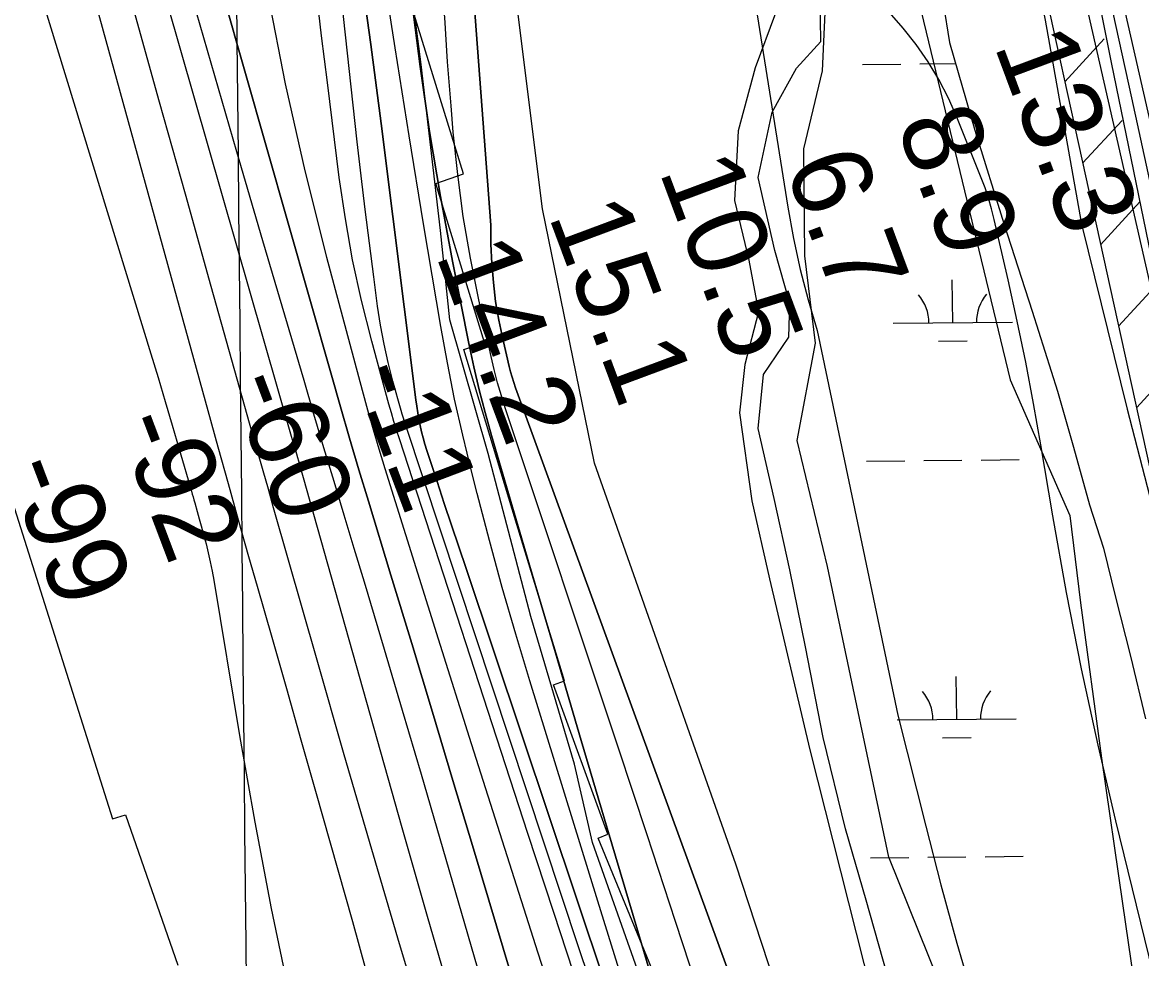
# Model space of a CAD drawing. Extents: x 3625074 to 3663148, y 511451 to 537151.
# Drawn here: x 3634334 to 3635272, y 523291 to 524076 of the extents above; entities that cross this region are included whole.
import ezdxf

# ---------------------------------------------------------------- set-up
doc = ezdxf.new("R2010")
doc.units = 0
for name, color, linetype in [('V-BORW-LINE', 7, 'Continuous'), ('V-FLOD-BASE', 7, 'Continuous'), ('V-GRID-MAJR', 7, 'Continuous'), ('V-LEVE-TOET', 7, 'Continuous'), ('V-RIVR-EDGE', 7, 'Continuous'), ('V-RIVR-RANG', 7, 'Continuous'), ('V-ROAD-CNTR', 7, 'Continuous'), ('V-RRAP-FSHR', 7, 'Continuous'), ('V-RRAP-RVMT', 7, 'Continuous'), ('V-SITE-VEGE', 7, 'Continuous'), ('V-SURV-LINE', 7, 'Continuous'), ('V-TOPO-DPTH', 7, 'Continuous'), ('V-TOPO-MAJR', 7, 'Continuous'), ('V-TOPO-MINR', 7, 'Continuous'), ('V-TOPO-WATR', 7, 'Continuous'), ('V-WETL-SWMP', 7, 'Continuous')]:
    doc.layers.add(name, color=color, linetype=linetype)

msp = doc.modelspace()

# ---------------------------------------------------------------- linework, layer by layer
at = {"layer": 'V-BORW-LINE'}
msp.add_lwpolyline([(3635135.42, 523189.52), (3635060.21, 523376.18), (3635008.87, 523620.11), (3634983.37, 523725.78), (3634998.84, 523807.41), (3634989.96, 523880.66), (3634989.06, 523970.28), (3635004.7, 524035.62), (3635011.38, 524182.35), (3634977.64, 524296.09), (3634968.43, 524401.92), (3634984.32, 524442.82), (3635008.84, 524434.92), (3635033.61, 524402.58), (3635050.72, 524321.27), (3635059.77, 524231.73), (3635085.6, 524093.47), (3635162.12, 523776.46), (3635212.15, 523662.89), (3635221.03, 523589.64), (3635238.63, 523459.45), (3635256.15, 523337.4), (3635282.39, 523158.41)], dxfattribs=at)
at = {"layer": 'V-FLOD-BASE'}
msp.add_lwpolyline([(3635088.85, 524732.57), (3635135.28, 524536.62), (3635174.93, 524366.83), (3635209.04, 524231.05), (3635246.81, 524042.7), (3635280.14, 523880.8)], dxfattribs=at)
at = {"layer": 'V-GRID-MAJR'}
msp.add_spline([(3634583.66, 516913.04), (3634524.61, 522971.79), (3634465.55, 529032.47), (3634406.49, 535093.17), (3634406.47, 535095.09)], degree=3, dxfattribs=at)
at = {"layer": 'V-LEVE-TOET'}
msp.add_lwpolyline([(3635064.8, 524659.03), (3635094.14, 524546.21), (3635125.53, 524397.38), (3635160.9, 524235.18), (3635191.36, 524078.23), (3635222.01, 523907.06), (3635260.32, 523752.09), (3635297.55, 523607.28)], dxfattribs=at)
at = {"layer": 'V-RIVR-EDGE'}
msp.add_lwpolyline([(3634849.5, 523281.91), (3634811.77, 523388.62), (3634796.62, 523454.22), (3634760.16, 523578.08), (3634724.35, 523714.81), (3634692.15, 523827.01), (3634684.37, 523901.79), (3634668.17, 524040.92), (3634659.75, 524105.89), (3634647.21, 524237.04), (3634642.6, 524355.31), (3634629.99, 524460.12), (3634608.23, 524582.1)], dxfattribs=at)
at = {"layer": 'V-ROAD-CNTR'}
msp.add_lwpolyline([(3635138.94, 524570.37), (3635155.25, 524500.89), (3635189.26, 524351.75), (3635229.41, 524169.77), (3635263.93, 524013.09), (3635304.9, 523824.43), (3635347.31, 523635.48), (3635391.23, 523453.76), (3635441.04, 523243.56)], dxfattribs=at)
at = {"layer": 'V-RRAP-FSHR'}
for p, q in [((3635207.83, 524026.59), (3635240.88, 524062.53)), ((3635222.86, 523958.22), (3635255.91, 523994.17)), ((3635237.89, 523889.86), (3635270.94, 523925.8)), ((3635252.92, 523821.49), (3635285.97, 523857.43)), ((3635267.95, 523753.12), (3635301, 523789.06))]:
    msp.add_line(p, q, dxfattribs=at)
msp.add_lwpolyline([(3635086.48, 524584.28), (3635168.39, 524205.98), (3635317.67, 523526.98)], dxfattribs=at)
at = {"layer": 'V-RRAP-RVMT'}
for p, q in [((3634703.76, 523949.28), (3634661.9, 524083.9)), ((3634680.5, 523941.35), (3634703.76, 523949.28)), ((3634721.19, 523807.95), (3634680.5, 523941.35)), ((3634703.88, 523801.95), (3634721.19, 523807.95)), ((3634744.52, 523668.11), (3634703.88, 523801.95)), ((3634318.88, 523695.23), (3634409.45, 523408.4)), ((3634788.48, 523524.06), (3634744.52, 523668.11)), ((3634779.08, 523520.69), (3634788.48, 523524.06)), ((3634824.64, 523395.49), (3634779.08, 523520.69)), ((3634409.45, 523408.4), (3634420.15, 523411.69)), ((3634420.15, 523411.69), (3634464.19, 523285.78)), ((3634816.51, 523392.12), (3634824.64, 523395.49)), ((3634865.81, 523272.65), (3634816.51, 523392.12))]:
    msp.add_line(p, q, dxfattribs=at)
at = {"layer": 'V-SITE-VEGE'}
for points in [[(3635308.56, 522409.94), (3635214.7, 522580.75), (3635170.06, 522757.64), (3635133.76, 522861.91), (3635073.69, 523022.79), (3634991.88, 523187.87), (3634931.97, 523370.51), (3634874.33, 523533.79), (3634813.54, 523706.77), (3634769.98, 523919.93), (3634747.92, 524096.65), (3634719.39, 524270.2), (3634687.06, 524476.83), (3634649.73, 524660.11)], [(3634965.37, 524084.04), (3634948.33, 524038.27), (3634934.02, 523985.51), (3634930.79, 523927.11), (3634942.93, 523876.94), (3634950.94, 523833.75), (3634939.48, 523789.32), (3634935, 523749.01), (3634945.56, 523675.2), (3634960.37, 523609.71), (3634994.06, 523466.17), (3635052.12, 523236.19)]]:
    msp.add_lwpolyline(points, dxfattribs=at)
at = {"layer": 'V-SURV-LINE'}
for points in [[(3635222.15, 524243.88), (3635463.94, 523183.7)], [(3635434.69, 523177.04), (3635192.89, 524237.22)]]:
    msp.add_lwpolyline(points, dxfattribs=at)
at = {"layer": 'V-TOPO-DPTH'}
for points in [[(3634629.2, 524637.68), (3634646.61, 524565.11), (3634665.46, 524486.45), (3634673.1, 524453.14), (3634680.33, 524419.75), (3634686.91, 524386.23), (3634693.08, 524352.62), (3634726.47, 523906.35), (3634726.69, 523890.3), (3634727.33, 523874.25), (3634728.7, 523858.26), (3634730.61, 523842.35), (3634733.33, 523826.55), (3634736.6, 523810.84), (3634741.98, 523787.86), (3634743.15, 523783.28), (3634744.41, 523778.74), (3634745.85, 523774.24), (3634747.38, 523769.77), (3634958.05, 523191.96)], [(3634806.91, 523065.95), (3634712.07, 523383.14), (3634694.85, 523440.58), (3634677.58, 523498), (3634660.22, 523555.39), (3634642.81, 523612.77), (3634623.92, 523674.9), (3634615.99, 523701.22), (3634608.15, 523727.57), (3634600.47, 523753.97), (3634592.87, 523780.39), (3634465.87, 524226.88), (3634460.23, 524247.06), (3634454.7, 524267.28), (3634449.35, 524287.54), (3634444.12, 524307.83), (3634439.07, 524328.17), (3634434.13, 524348.54), (3634429.36, 524368.95), (3634424.72, 524389.38), (3634400.19, 524499.42), (3634383.48, 524574.93)], [(3634383.48, 524574.93), (3634400.19, 524499.42), (3634424.72, 524389.38), (3634429.36, 524368.95), (3634434.13, 524348.54), (3634439.07, 524328.17), (3634444.12, 524307.83), (3634449.35, 524287.54), (3634454.7, 524267.28), (3634460.23, 524247.06), (3634465.87, 524226.88), (3634592.87, 523780.39), (3634600.47, 523753.97), (3634608.15, 523727.57), (3634615.99, 523701.22), (3634623.92, 523674.9), (3634642.81, 523612.77), (3634660.22, 523555.39), (3634677.58, 523498), (3634694.85, 523440.58), (3634712.07, 523383.14), (3634806.91, 523065.95)], [(3634616.78, 524124.36), (3634625.89, 524057.91), (3634634.58, 523991.41), (3634663.77, 523759.74), (3634664.51, 523754.37), (3634665.33, 523749.02), (3634666.26, 523743.68), (3634667.27, 523738.36), (3634668.43, 523733.07), (3634669.72, 523727.81), (3634671.2, 523722.61), (3634672.81, 523717.44), (3634681.48, 523691.23), (3634687.53, 523672.99), (3634693.59, 523654.75), (3634699.67, 523636.51), (3634705.77, 523618.28), (3634845.4, 523201.46)], [(3634845.4, 523201.46), (3634705.77, 523618.28), (3634699.67, 523636.51), (3634693.59, 523654.75), (3634687.53, 523672.99), (3634681.48, 523691.23), (3634672.81, 523717.44), (3634671.2, 523722.61), (3634669.72, 523727.81), (3634668.43, 523733.07), (3634667.27, 523738.36), (3634666.26, 523743.68), (3634665.33, 523749.02), (3634664.51, 523754.37), (3634663.77, 523759.74), (3634634.58, 523991.41), (3634625.89, 524057.91), (3634616.78, 524124.36)], [(3634539.97, 524098.2), (3634554.15, 524024.83), (3634570.7, 523951.96), (3634588.83, 523879.42), (3634618.66, 523767.79), (3634623.17, 523751.35), (3634627.81, 523734.94), (3634632.67, 523718.6), (3634637.67, 523702.3), (3634682.54, 523559.28), (3634710.19, 523471.53), (3634737.98, 523383.82), (3634765.98, 523296.19), (3634794.13, 523208.6)], [(3634539.97, 524098.2), (3634554.15, 524024.83), (3634570.7, 523951.96), (3634588.83, 523879.42), (3634618.66, 523767.79), (3634623.17, 523751.35), (3634627.81, 523734.94), (3634632.67, 523718.6), (3634637.67, 523702.3), (3634682.54, 523559.28), (3634710.19, 523471.53), (3634737.98, 523383.82), (3634765.98, 523296.19), (3634794.13, 523208.6)], [(3634801.29, 523263.46), (3634779.28, 523329.78), (3634757.5, 523396.18), (3634649.87, 523727.06), (3634647.58, 523734.29), (3634645.35, 523741.55), (3634643.23, 523748.83), (3634641.18, 523756.14), (3634626.71, 523809.08), (3634618.21, 523843.02), (3634610.68, 523877.16), (3634604.6, 523911.58), (3634599.5, 523946.19), (3634589.48, 524025.89), (3634584.68, 524065.17), (3634580.07, 524104.47)], [(3634801.29, 523263.46), (3634779.28, 523329.78), (3634757.5, 523396.18), (3634649.87, 523727.06), (3634647.58, 523734.29), (3634645.35, 523741.55), (3634643.23, 523748.83), (3634641.18, 523756.14), (3634626.71, 523809.08), (3634618.21, 523843.02), (3634610.68, 523877.16), (3634604.6, 523911.58), (3634599.5, 523946.19), (3634589.48, 524025.89), (3634584.68, 524065.17), (3634580.07, 524104.47)], [(3634660.21, 524093.88), (3634667.3, 524039.23), (3634675.23, 523984.71), (3634684.44, 523930.39), (3634694.49, 523876.21), (3634708.18, 523806.95), (3634712.29, 523787.56), (3634716.74, 523768.25), (3634721.73, 523749.08), (3634727.06, 523729.99), (3634759.1, 523621.09), (3634780.74, 523547.62), (3634802.41, 523474.16), (3634824.12, 523400.71), (3634845.86, 523327.27), (3634930.83, 523040.51)], [(3634930.83, 523040.51), (3634845.86, 523327.27), (3634824.12, 523400.71), (3634802.41, 523474.16), (3634780.74, 523547.62), (3634759.1, 523621.09), (3634727.06, 523729.99), (3634721.73, 523749.08), (3634716.74, 523768.25), (3634712.29, 523787.56), (3634708.18, 523806.95), (3634694.49, 523876.21), (3634684.44, 523930.39), (3634675.23, 523984.71), (3634667.3, 524039.23), (3634660.21, 524093.88)], [(3634949.86, 524082.71), (3634975.68, 523921.26), (3634980.46, 523895.14), (3634986.01, 523869.21), (3634992.73, 523843.55), (3635000.22, 523818.08), (3635067.97, 523495.35), (3635091.29, 523402.29), (3635104.07, 523353.16), (3635117.43, 523304.19), (3635131.67, 523255.48)], [(3635306.37, 523179.81), (3635250.75, 523406.7), (3635235.89, 523470.35), (3635221.95, 523534.2), (3635209.43, 523598.33), (3635197.84, 523662.66), (3635187.8, 523722.1), (3635181.63, 523756.8), (3635175.07, 523791.42), (3635167.92, 523825.92), (3635160.37, 523860.34), (3635148.77, 523911.14), (3635146.52, 523920.04), (3635143.99, 523928.85), (3635141.05, 523937.53), (3635137.83, 523946.12), (3635117.45, 523996.91), (3635110.3, 524012.91), (3635102.36, 524028.47), (3635093.25, 524043.37), (3635083.36, 524057.84), (3635072.39, 524071.5), (3635060.77, 524084.55)]]:
    msp.add_lwpolyline(points, dxfattribs=at)
at = {"layer": 'V-TOPO-MAJR'}
msp.add_lwpolyline([(3634715.28, 523283.77), (3634699.8, 523337.72), (3634684.21, 523391.63), (3634668.45, 523445.49), (3634652.57, 523499.32), (3634637.38, 523550.55), (3634628.99, 523578.73), (3634620.57, 523606.9), (3634612.11, 523635.06), (3634603.6, 523663.2), (3634595.11, 523691.35), (3634586.66, 523719.52), (3634578.29, 523747.7), (3634569.95, 523775.9), (3634535.42, 523893.29), (3634513.63, 523967.75), (3634491.98, 524042.25), (3634470.54, 524116.81)], dxfattribs=at)
at = {"layer": 'V-TOPO-MINR'}
for points in [[(3634905.24, 523249.83), (3634881.5, 523322.46), (3634857.59, 523395.03), (3634833.56, 523467.56), (3634738.84, 523752.3), (3634735.41, 523763.17), (3634732.21, 523774.12), (3634729.37, 523785.15), (3634726.76, 523796.26), (3634716.41, 523843.61), (3634709.48, 523878.54), (3634703.47, 523913.6), (3634698.82, 523948.88), (3634695.08, 523984.29), (3634693.2, 524006.27), (3634690.38, 524043.29), (3634688.05, 524080.34), (3634653.48, 524393.21), (3634649.75, 524410.88), (3634645.6, 524428.45), (3634641.17, 524445.97), (3634548.09, 524797.05)], [(3634695.04, 523252.55), (3634673.56, 523326.65), (3634652.37, 523400.84), (3634566.36, 523705.29), (3634565.51, 523708.28), (3634564.66, 523711.26), (3634563.81, 523714.25), (3634562.95, 523717.24), (3634562.09, 523720.23), (3634561.24, 523723.21), (3634560.38, 523726.2), (3634559.52, 523729.18), (3634396.66, 524296.85), (3634391.31, 524315.74), (3634386.05, 524334.66), (3634380.93, 524353.62), (3634375.91, 524372.61), (3634291.59, 524695.69)], [(3634673.77, 523224.53), (3634650.1, 523303.64), (3634626.68, 523382.83), (3634603.63, 523462.13), (3634580.82, 523541.5), (3634544.42, 523669.33), (3634540.01, 523684.84), (3634535.61, 523700.35), (3634531.23, 523715.87), (3634526.86, 523731.39), (3634492.12, 523854.94), (3634470.43, 523932.25), (3634448.77, 524009.57), (3634427.19, 524086.9), (3634405.64, 524164.25), (3634377.95, 524263.81), (3634369.19, 524295.54), (3634360.49, 524327.28), (3634351.89, 524359.05), (3634343.36, 524390.84), (3634269.2, 524668.98)], [(3634958.05, 523191.96), (3634747.38, 523769.77), (3634745.85, 523774.24), (3634744.41, 523778.74), (3634743.15, 523783.28), (3634741.98, 523787.86), (3634736.6, 523810.84), (3634733.33, 523826.55), (3634730.61, 523842.35), (3634728.7, 523858.26), (3634727.33, 523874.25), (3634726.69, 523890.3), (3634726.47, 523906.35), (3634693.08, 524352.62), (3634686.91, 524386.23), (3634680.33, 524419.75), (3634673.1, 524453.14), (3634665.46, 524486.45), (3634646.61, 524565.11), (3634629.2, 524637.68)], [(3634806.91, 523065.95), (3634712.07, 523383.14), (3634694.85, 523440.58), (3634677.58, 523498), (3634660.22, 523555.39), (3634642.81, 523612.77), (3634623.92, 523674.9), (3634615.99, 523701.22), (3634608.15, 523727.57), (3634600.47, 523753.97), (3634592.87, 523780.39), (3634465.87, 524226.88), (3634460.23, 524247.06), (3634454.7, 524267.28), (3634449.35, 524287.54), (3634444.12, 524307.83), (3634439.07, 524328.17), (3634434.13, 524348.54), (3634429.36, 524368.95), (3634424.72, 524389.38), (3634400.19, 524499.42), (3634383.48, 524574.93)], [(3634622.15, 523281.25), (3634610.85, 523321.96), (3634579.82, 523431.48), (3634567.62, 523474.47), (3634555.4, 523517.46), (3634543.15, 523560.44), (3634530.89, 523603.41), (3634523.77, 523628.29), (3634515.09, 523658.84), (3634506.47, 523689.39), (3634497.93, 523719.98), (3634489.46, 523750.58), (3634353.61, 524243.77), (3634350.15, 524256.36), (3634346.69, 524268.95), (3634343.24, 524281.54), (3634339.8, 524294.13), (3634334.4, 524313.87), (3634333.66, 524316.59)], [(3634298.19, 524265.27), (3634441.41, 523798.43), (3634447.49, 523778.46), (3634453.5, 523758.47), (3634459.44, 523738.45), (3634465.31, 523718.42), (3634475.53, 523683.27), (3634476.24, 523680.8), (3634476.96, 523678.33), (3634477.67, 523675.86), (3634478.38, 523673.38), (3634480.43, 523666.22), (3634482.14, 523660.15), (3634483.81, 523654.08), (3634485.44, 523648), (3634487.04, 523641.91), (3634487.79, 523639), (3634489.63, 523631.42), (3634491.35, 523623.82), (3634492.86, 523616.17), (3634494.24, 523608.5), (3634515.88, 523478.34), (3634528.69, 523405.71), (3634542.44, 523333.27), (3634557.6, 523261.11)], [(3634844.29, 523249.41), (3634830.19, 523294.38), (3634816.22, 523339.39), (3634759.28, 523524.16), (3634747.56, 523563.22), (3634736.22, 523602.38), (3634725.47, 523641.71), (3634715.1, 523681.15), (3634710.27, 523700.1), (3634702.99, 523730.22), (3634696.21, 523760.45), (3634690.18, 523790.83), (3634684.65, 523821.33), (3634670.14, 523907.48), (3634658.01, 523981.17), (3634646.24, 524054.91), (3634635.02, 524128.74)], [(3634845.4, 523201.46), (3634705.77, 523618.28), (3634699.67, 523636.51), (3634693.59, 523654.75), (3634687.53, 523672.99), (3634681.48, 523691.23), (3634672.81, 523717.44), (3634671.2, 523722.61), (3634669.72, 523727.81), (3634668.43, 523733.07), (3634667.27, 523738.36), (3634666.26, 523743.68), (3634665.33, 523749.02), (3634664.51, 523754.37), (3634663.77, 523759.74), (3634634.58, 523991.41), (3634625.89, 524057.91), (3634616.78, 524124.36)], [(3634801.29, 523263.46), (3634779.28, 523329.78), (3634757.5, 523396.18), (3634649.87, 523727.06), (3634647.58, 523734.29), (3634645.35, 523741.55), (3634643.23, 523748.83), (3634641.18, 523756.14), (3634626.71, 523809.08), (3634618.21, 523843.02), (3634610.68, 523877.16), (3634604.6, 523911.58), (3634599.5, 523946.19), (3634589.48, 524025.89), (3634584.68, 524065.17), (3634580.07, 524104.47)], [(3634817.11, 523250.55), (3634800.5, 523300.18), (3634655.26, 523738.19), (3634654.24, 523741.35), (3634653.25, 523744.52), (3634652.3, 523747.7), (3634651.38, 523750.9), (3634644.54, 523775.45), (3634640.56, 523791), (3634637.02, 523806.63), (3634634.13, 523822.4), (3634631.68, 523838.26), (3634628.4, 523862.91), (3634624.74, 523891.18), (3634621.2, 523919.46), (3634617.85, 523947.76), (3634614.63, 523976.08), (3634601.3, 524096.89)], [(3634949.86, 524082.71), (3634975.68, 523921.26), (3634980.46, 523895.14), (3634986.01, 523869.21), (3634992.73, 523843.55), (3635000.22, 523818.08), (3635067.97, 523495.35), (3635091.29, 523402.29), (3635104.07, 523353.16), (3635117.43, 523304.19), (3635131.67, 523255.48)], [(3635306.37, 523179.81), (3635250.75, 523406.7), (3635235.89, 523470.35), (3635221.95, 523534.2), (3635209.43, 523598.33), (3635197.84, 523662.66), (3635187.8, 523722.1), (3635181.63, 523756.8), (3635175.07, 523791.42), (3635167.92, 523825.92), (3635160.37, 523860.34), (3635148.77, 523911.14), (3635146.52, 523920.04), (3635143.99, 523928.85), (3635141.05, 523937.53), (3635137.83, 523946.12), (3635117.45, 523996.91), (3635110.3, 524012.91), (3635102.36, 524028.47), (3635093.25, 524043.37), (3635083.36, 524057.84), (3635072.39, 524071.5), (3635060.77, 524084.55)]]:
    msp.add_lwpolyline(points, dxfattribs=at)
at = {"layer": 'V-TOPO-WATR'}
msp.add_lwpolyline([(3634930.83, 523040.51), (3634845.86, 523327.27), (3634824.12, 523400.71), (3634802.41, 523474.16), (3634780.74, 523547.62), (3634759.1, 523621.09), (3634727.06, 523729.99), (3634721.73, 523749.08), (3634716.74, 523768.25), (3634712.29, 523787.56), (3634708.18, 523806.95), (3634694.49, 523876.21), (3634684.44, 523930.39), (3634675.23, 523984.71), (3634667.3, 524039.23), (3634660.21, 524093.88)], dxfattribs=at)
at = {"layer": 'V-WETL-SWMP'}
for p, q in [((3635038.32, 524041.04), (3635070.32, 524041.36)), ((3635086.32, 524041.52), (3635116.37, 524041.82)), ((3635113.9, 523824.54), (3635113.54, 523860.54)), ((3635063.91, 523824.04), (3635163.9, 523825.05)), ((3635102.06, 523808.99), (3635126.06, 523809.23)), ((3635041.66, 523708.38), (3635073.66, 523708.7)), ((3635089.65, 523708.86), (3635121.65, 523709.18)), ((3635137.65, 523709.35), (3635169.65, 523709.67)), ((3635117.24, 523491.89), (3635116.88, 523527.88)), ((3635067.24, 523491.38), (3635167.24, 523492.39)), ((3635105.4, 523476.34), (3635129.4, 523476.58)), ((3635045, 523375.72), (3635076.99, 523376.04)), ((3635092.99, 523376.21), (3635124.99, 523376.53)), ((3635140.99, 523376.69), (3635172.99, 523377.01))]:
    msp.add_line(p, q, dxfattribs=at)
for points in [[(3635100.45, 524125.79), (3635111.24, 524059.6), (3635132.46, 523986.08), (3635156.87, 523907.7), (3635180.51, 523834.16), (3635201.77, 523767.09), (3635215.13, 523720.23), (3635228.47, 523671.76), (3635240.3, 523635.39), (3635250.47, 523594.2), (3635263, 523544.92), (3635275.51, 523492.43)], [(3635062.59, 523265.06), (3635041.38, 523340.19), (3635024.09, 523399.98), (3635005.32, 523476.71), (3634990.56, 523552.6), (3634977.34, 523617.19), (3634964.08, 523676.95), (3634950.81, 523735.9), (3634955.18, 523781.02), (3634976.38, 523812.3), (3634977.39, 523840.51), (3634964.82, 523884.94), (3634950.77, 523946.32), (3634962.46, 524001.05), (3634982.9, 524037.99), (3635003.22, 524060.41), (3635002.69, 524097.5)]]:
    msp.add_lwpolyline(points, dxfattribs=at)
for centre, start, end in [((3635058.66, 523824.46), 359.8032, 41.34685), ((3635169.14, 523825.57), 139.80319, 181.34685), ((3635172.48, 523492.92), 139.80319, 181.34685), ((3635062, 523491.81), 359.8032, 41.34685)]:
    msp.add_arc(centre, 35.25, start, end, dxfattribs=at)

# ---------------------------------------------------------------- texts
at = {"layer": 'V-RIVR-RANG'}
for s, rotation, p in [('13.3', 290.43833, (3635148.25, 524057.28)), ('8.9', 290.43833, (3635066.15, 523991.23)), ('6.7', 290.43833, (3634972.62, 523955.83)), ('10.5', 290.43833, (3634867.4, 523951.82)), ('15.1', 290.43833, (3634774.61, 523914.44)), ('14.2', 290.43833, (3634680.16, 523881.51)), ('-11', 290.72286, (3634610.13, 523782.34)), ('-60', 290.72286, (3634506.43, 523773.84)), ('-92', 290.72286, (3634412.16, 523740.41)), ('-99', 290.72286, (3634319.57, 523702.54))]:
    msp.add_text(s, height=67, rotation=rotation, dxfattribs=at).set_placement(p)

doc.saveas('drawing.dxf')
